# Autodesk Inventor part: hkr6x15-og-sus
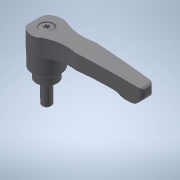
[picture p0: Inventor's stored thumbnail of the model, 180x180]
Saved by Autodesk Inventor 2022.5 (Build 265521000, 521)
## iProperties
Created: 2017-09
Part Number: hkr6x15-og-sus
Material: 一般
Document SubType Name: Modeling
Designer: imaocorp
Density: 1 g/cm^3
Appearance: 既定
Author: imaocorp
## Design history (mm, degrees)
node "hkr6x15-og-sus.x_t1"
node "hkr6x15-og-sus"
node "Base1"
